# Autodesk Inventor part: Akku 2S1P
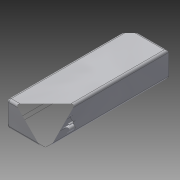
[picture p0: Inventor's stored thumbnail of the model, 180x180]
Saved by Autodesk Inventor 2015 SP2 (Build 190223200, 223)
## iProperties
Created: 2012-08
Part Number: Akku 2S1P
Material: LCP-Kunststoff
Document SubType Name: Modeling
Designer: rYan
Mass: 131.468 g
Surface Area: 137.12 cm^2
Volume: 80.8535 cm^3
Density: 1.626 g/cm^3
Appearance: Glatt - weiß
Author: rYan
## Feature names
1. Extrusion1
2. Rundung1 [Fillet]
3. Sweeping1
4. Sweeping2
5. Spiegeln1 [Mirror]
## Parameters: d0 = 34 mm, d2 = 108 mm, d3 = 22 mm, d4 = 0, d5 = 2 mm, d6 = 2 mm, d8 = 2 mm, d9 = 1.5 mm, d11 = 18 mm, d12 = 0, d16 = 3 mm, d18 = 2 mm, d20 = 2 mm, d21 = 90 deg, d22 = 18 mm, d23 = 4 mm, d25 = 0, d26 = 0, d27 = 0
